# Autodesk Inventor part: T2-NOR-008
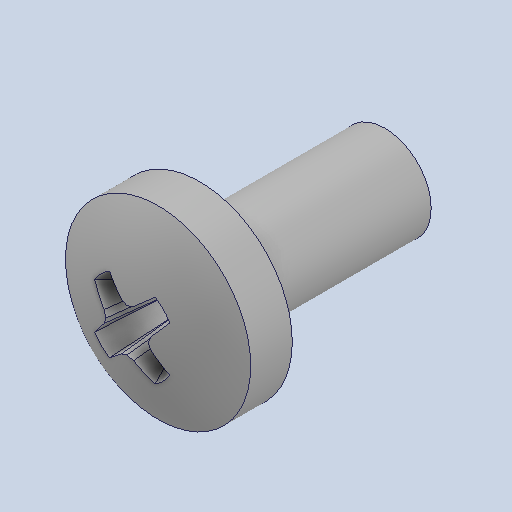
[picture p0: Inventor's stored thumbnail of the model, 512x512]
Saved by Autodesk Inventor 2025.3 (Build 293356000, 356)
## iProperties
Created: 2026-10
Part Number: T2-NOR-008
Material: Genérico
Document SubType Name: Modeling
Designer: Luis MuÃ±oz
Density: 1 g/cm^3
Appearance: Valor por defecto
Project: TESIS 2 - Plataforma mecatrÃ³nica preventiva desacoplada
Description: Tornillo M2 × 4 mm
Author: Luis M
Title: Tornillo M2 Ã— 4 mm
Revision Number: 00
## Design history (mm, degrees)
feature "Base1"
node "Sólido1"
